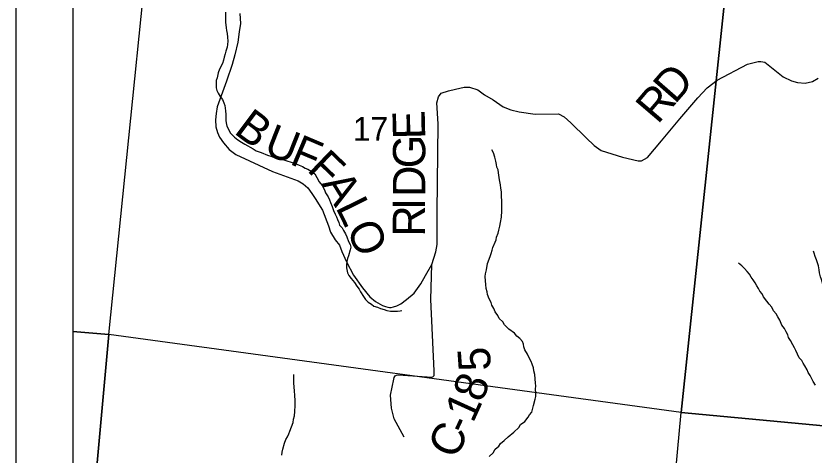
# Model space of a CAD drawing. Extents: x 0 to 34, y 0 to 22.
# Drawn here: x 2 to 3.401, y 15.353 to 16.124 of the extents above; entities that cross this region are included whole.
import ezdxf

# ---------------------------------------------------------------- set-up
doc = ezdxf.new("R2010")
doc.units = 0
for name, color, linetype in [('Default', 7, 'Continuous'), ('GM_X_County_Road', 7, 'Continuous'), ('GM_X_County_Road_Text', 7, 'Continuous'), ('GM_X_Minor_River', 7, 'Continuous'), ('GM_X_Section', 7, 'Continuous'), ('GM_X_Section_Text', 7, 'Continuous'), ('GM_X_State_Route', 7, 'Continuous'), ('SH_Data', 7, 'Continuous')]:
    doc.layers.add(name, color=color, linetype=linetype)

msp = doc.modelspace()

# ---------------------------------------------------------------- linework, layer by layer
at = {"layer": 'Default'}
for points in [[(2.1, 16.5512), (2.1, 15.5702), (2.1629, 15.5646), (2.2623, 16.5381)], [(2.1, 15.5702), (2.1, 14.8697), (2.1629, 15.5646)], [(2.1, 14.8697), (2.1, 14.5322), (3.0761, 14.4328), (3.1681, 15.4277), (2.1629, 15.5646)]]:
    msp.add_lwpolyline(points, close=True, dxfattribs=at)
at = {"layer": 'GM_X_County_Road'}
for points in [[(2.3932, 16.1285), (2.3942, 16.111), (2.3919, 16.0962), (2.3896, 16.0781), (2.3844, 16.0558), (2.3794, 16.0389), (2.3695, 16.0095), (2.3531, 15.9648), (2.3513, 15.953), (2.3502, 15.9417), (2.351, 15.9295), (2.3538, 15.9196), (2.3574, 15.9111), (2.3647, 15.901), (2.3742, 15.8898), (2.3861, 15.8807), (2.4506, 15.8509), (2.4954, 15.8346), (2.5043, 15.8294), (2.5125, 15.822), (2.5194, 15.8123), (2.5253, 15.8038), (2.5384, 15.7833), (2.5487, 15.7553), (2.5525, 15.7446), (2.5605, 15.7311), (2.5679, 15.7218), (2.5725, 15.7103), (2.5804, 15.6922), (2.5926, 15.6688), (2.6087, 15.6467), (2.6216, 15.6308), (2.6316, 15.6225), (2.6436, 15.6154), (2.6487, 15.6136), (2.6532, 15.6125), (2.6561, 15.612), (2.6588, 15.6121), (2.663, 15.6132), (2.6687, 15.6153), (2.6759, 15.6183), (2.6856, 15.6261), (2.6992, 15.6371), (2.7107, 15.6535), (2.7194, 15.6681), (2.7302, 15.6879), (2.7376, 15.7101), (2.7395, 15.723), (2.7399, 15.7795), (2.7414, 15.9344), (2.7393, 15.9717), (2.7419, 15.9822), (2.7466, 15.9885), (2.7593, 15.9928), (2.7719, 15.9955), (2.7871, 15.9989), (2.7962, 15.999), (2.8109, 15.9941), (2.8225, 15.9858), (2.8382, 15.977), (2.8557, 15.9644), (2.8692, 15.9595), (2.8835, 15.9557), (2.9115, 15.9519), (2.9525, 15.9524), (2.9626, 15.9472), (2.9745, 15.9366), (3.0015, 15.9101), (3.0155, 15.8964), (3.0278, 15.8881), (3.0651, 15.8761), (3.0926, 15.8697), (3.0987, 15.8699), (3.1091, 15.8753), (3.1334, 15.9047), (3.166, 15.9437), (3.1974, 15.9805), (3.2138, 15.9979), (3.2312, 16.0115), (3.2844, 16.0393), (3.3031, 16.0441), (3.308, 16.044), (3.3152, 16.0427), (3.3475, 16.0171), (3.3618, 16.0103), (3.3727, 16.007), (3.3859, 16.0059), (3.3986, 16.0093), (3.409, 16.0148)], [(2.6818, 15.3843), (2.6644, 15.4163), (2.6596, 15.4354), (2.658, 15.4582), (2.6633, 15.4862), (2.6644, 15.4894), (2.6661, 15.4918), (2.6685, 15.4934), (2.6711, 15.4939), (2.6798, 15.4933), (2.7302, 15.4897), (2.7318, 15.4903), (2.7334, 15.4914), (2.7341, 15.4925), (2.7343, 15.4935), (2.7345, 15.4956), (2.7346, 15.501), (2.7285, 15.6264), (2.7302, 15.6879)]]:
    msp.add_lwpolyline(points, dxfattribs=at)
at = {"layer": 'GM_X_Minor_River'}
for points in [[(2.3681, 16.1308), (2.3677, 16.1179), (2.3679, 16.1129), (2.3685, 16.1083), (2.3691, 16.1034), (2.37, 16.0988), (2.3706, 16.0935), (2.3715, 16.087), (2.372, 16.0797), (2.3715, 16.074), (2.3706, 16.0695), (2.3688, 16.0624), (2.3675, 16.0575), (2.3658, 16.0518), (2.3644, 16.0462), (2.3627, 16.0405), (2.3575, 16.0305), (2.3553, 16.0241), (2.3535, 16.0154), (2.3518, 16.0105), (2.3514, 15.998), (2.3528, 15.993), (2.3549, 15.9884), (2.3588, 15.9826), (2.3625, 15.9775), (2.3653, 15.9713), (2.3667, 15.9667), (2.3676, 15.9621), (2.3682, 15.9572), (2.3684, 15.9511), (2.3686, 15.9458), (2.3688, 15.9408), (2.3694, 15.9362), (2.3704, 15.9305), (2.3732, 15.9251), (2.376, 15.9189), (2.3837, 15.9111), (2.3897, 15.9067), (2.3963, 15.9023), (2.4019, 15.899), (2.4168, 15.8909), (2.422, 15.887), (2.4307, 15.8844)], [(2.4307, 15.8844), (2.4419, 15.8798), (2.4475, 15.8777), (2.4535, 15.8756), (2.461, 15.8734), (2.4705, 15.8712), (2.4757, 15.8695), (2.4832, 15.8674), (2.493, 15.864), (2.4975, 15.8623), (2.5031, 15.8595), (2.5079, 15.857), (2.5124, 15.855), (2.5184, 15.8513), (2.5247, 15.8466), (2.5286, 15.8403), (2.5325, 15.8326), (2.5376, 15.8264), (2.5419, 15.8186), (2.5437, 15.8136), (2.5483, 15.8062), (2.5504, 15.8012), (2.5522, 15.7966), (2.5554, 15.7897), (2.5578, 15.7827), (2.5606, 15.7758), (2.5627, 15.7712), (2.5644, 15.7666), (2.5669, 15.7615), (2.5683, 15.7569), (2.5727, 15.7522), (2.5752, 15.7476), (2.5784, 15.7414), (2.5812, 15.736), (2.584, 15.7279), (2.5869, 15.7229), (2.5878, 15.7183), (2.5869, 15.7134), (2.5839, 15.7028), (2.5822, 15.698), (2.5813, 15.6927), (2.5803, 15.6863), (2.5805, 15.6817), (2.5821, 15.6729), (2.5846, 15.6683), (2.5886, 15.6628), (2.5944, 15.6558), (2.5988, 15.6495), (2.6028, 15.6445), (2.6053, 15.6398), (2.6103, 15.6313), (2.6139, 15.6262), (2.6183, 15.6215), (2.6243, 15.6179), (2.6287, 15.6147), (2.6351, 15.6126), (2.64, 15.6105), (2.6463, 15.6084), (2.6512, 15.6071), (2.658, 15.6057), (2.6637, 15.6055), (2.6702, 15.6057), (2.6748, 15.6063), (2.6779, 15.6071)], [(2.8465, 15.854), (2.8447, 15.8587), (2.8441, 15.8632), (2.8424, 15.869), (2.8408, 15.8763), (2.8384, 15.8839), (2.8359, 15.889)], [(2.8311, 15.3505), (2.8382, 15.3568), (2.8418, 15.3631), (2.8481, 15.3686), (2.8509, 15.3734), (2.8575, 15.3785), (2.8646, 15.3847), (2.8744, 15.3931), (2.883, 15.4012), (2.8862, 15.4068), (2.8936, 15.4118), (2.8996, 15.4192), (2.9016, 15.4237), (2.9059, 15.4285), (2.909, 15.4402), (2.912, 15.4511), (2.913, 15.456), (2.9132, 15.462), (2.9126, 15.4689), (2.9128, 15.4746), (2.9122, 15.4792), (2.9109, 15.4944), (2.9096, 15.5009), (2.9086, 15.5063), (2.9062, 15.5124), (2.9048, 15.517), (2.902, 15.5224), (2.898, 15.5302), (2.8934, 15.5379), (2.8916, 15.5429), (2.8911, 15.5479), (2.8897, 15.5525), (2.8846, 15.5576), (2.8798, 15.5619), (2.8754, 15.567), (2.8658, 15.5742), (2.8577, 15.5817), (2.8548, 15.5871), (2.8486, 15.593), (2.8461, 15.5981), (2.8414, 15.6043), (2.8393, 15.6101), (2.8357, 15.6159), (2.8343, 15.6209), (2.8311, 15.6271), (2.828, 15.6348), (2.8274, 15.6397), (2.8257, 15.6455), (2.8252, 15.6527), (2.8243, 15.6592), (2.8241, 15.6668), (2.8243, 15.6714), (2.8264, 15.6785), (2.8283, 15.6891), (2.8329, 15.7018), (2.8342, 15.7071), (2.8363, 15.7127), (2.8372, 15.7172), (2.8414, 15.7266), (2.843, 15.7311), (2.8436, 15.7356), (2.8468, 15.7424), (2.8482, 15.748), (2.8499, 15.7548), (2.8509, 15.7616), (2.8524, 15.7707), (2.8531, 15.7816), (2.8533, 15.7866), (2.8531, 15.7927), (2.8533, 15.7987), (2.8525, 15.8075), (2.8524, 15.8151), (2.8514, 15.8216), (2.8509, 15.8273), (2.8493, 15.8361), (2.8474, 15.8487), (2.8465, 15.854)], [(3.4456, 15.5812), (3.4372, 15.5871), (3.4324, 15.5922), (3.4288, 15.5969), (3.426, 15.6023), (3.4233, 15.6145), (3.4232, 15.6221), (3.4223, 15.6294), (3.4218, 15.6362), (3.4194, 15.6451), (3.4147, 15.6612), (3.413, 15.6662), (3.4113, 15.6731), (3.4103, 15.6784), (3.4091, 15.6853), (3.406, 15.6957), (3.4035, 15.7018), (3.4015, 15.7076), (3.4008, 15.7111)], [(3.4041, 15.4754), (3.3998, 15.482), (3.3977, 15.4867), (3.3945, 15.4929), (3.3912, 15.4979), (3.3895, 15.5025), (3.3852, 15.5095), (3.3823, 15.5142), (3.3798, 15.5192), (3.3754, 15.5239), (3.3722, 15.5301), (3.3694, 15.5366), (3.3669, 15.5413), (3.3644, 15.5463), (3.3602, 15.5544), (3.3565, 15.5595), (3.3552, 15.5641), (3.3523, 15.5695), (3.3495, 15.5753), (3.3451, 15.5812), (3.3413, 15.59), (3.338, 15.5955), (3.3352, 15.6009), (3.33, 15.6064), (3.3272, 15.6126), (3.3228, 15.618), (3.3188, 15.6231), (3.313, 15.6309), (3.3106, 15.6359), (3.3062, 15.641), (3.304, 15.6456), (3.3012, 15.6503), (3.2983, 15.6557), (3.2943, 15.6604), (3.2911, 15.6655), (3.2882, 15.6705), (3.2838, 15.6756), (3.2791, 15.6807), (3.2746, 15.685), (3.2691, 15.6898)], [(2.4671, 15.3529), (2.4677, 15.3582), (2.4686, 15.3635), (2.4717, 15.374), (2.4738, 15.3804), (2.477, 15.3848), (2.479, 15.3901), (2.4811, 15.395), (2.484, 15.4025), (2.4866, 15.4103), (2.4875, 15.416), (2.4889, 15.422), (2.4899, 15.4292), (2.4902, 15.4398), (2.4901, 15.4474), (2.4897, 15.4585), (2.4892, 15.4646), (2.4887, 15.4733), (2.4882, 15.4787), (2.488, 15.4851), (2.4881, 15.4897), (2.4879, 15.4942)]]:
    msp.add_lwpolyline(points, dxfattribs=at)
at = {"layer": 'GM_X_Section'}
msp.add_lwpolyline([(3.2644, 16.338), (3.1681, 15.4277), (2.1629, 15.5646), (2.2623, 16.5381)], dxfattribs=at)
for points in [[(3.2644, 16.338), (3.276, 16.3476), (3.3136, 16.3694), (3.3687, 16.3893), (4.2789, 16.3058), (4.1746, 15.3336), (3.1681, 15.4277)], [(4.1746, 15.3336), (4.0766, 14.3377), (3.0761, 14.4328), (3.1681, 15.4277)]]:
    msp.add_lwpolyline(points, close=True, dxfattribs=at)
at = {"layer": 'GM_X_State_Route'}
msp.add_lwpolyline([(2.1, 16.7408), (2.1, 14.1)], dxfattribs=at)
at = {"layer": 'SH_Data'}
for p, q in [((2, 21), (2, 14)), ((2.1, 20.9), (2.1, 14.1))]:
    msp.add_line(p, q, dxfattribs=at)

# ---------------------------------------------------------------- texts
at = {"layer": 'GM_X_County_Road_Text'}
for s, rotation, p in [('D', 48.9179, (3.1572, 15.9679)), ('R', 49.5135, (3.127, 15.9325)), ('B', 323.0466, (2.3808, 15.9192)), ('E', 91.2983, (2.7189, 15.9081)), ('U', 338.4962, (2.4326, 15.883)), ('F', 337.0603, (2.4788, 15.8648)), ('G', 89.8268, (2.7188, 15.8565)), ('F', 316.163, (2.5096, 15.8529)), ('D', 89.7591, (2.7186, 15.8064)), ('A', 301.8131, (2.5348, 15.8292)), ('L', 296.4036, (2.5605, 15.788)), ('I', 89.76, (2.7185, 15.7831)), ('R', 89.759, (2.7183, 15.7364)), ('O', 294.338, (2.5792, 15.7504)), ('5', 94.0844, (2.8345, 15.5024)), ('8', 69.663, (2.8187, 15.4436)), ('1', 65.5779, (2.8025, 15.4077)), ('-', 65.0109, (2.7924, 15.386)), ('C', 64.8773, (2.7725, 15.3436))]:
    msp.add_text(s, height=0.0568, rotation=rotation, dxfattribs=at).set_placement(p)
at = {"layer": 'GM_X_Section_Text'}
msp.add_text('17', height=0.04186, rotation=0, dxfattribs=at).set_placement((2.5915, 15.9049))

doc.saveas('drawing.dxf')
